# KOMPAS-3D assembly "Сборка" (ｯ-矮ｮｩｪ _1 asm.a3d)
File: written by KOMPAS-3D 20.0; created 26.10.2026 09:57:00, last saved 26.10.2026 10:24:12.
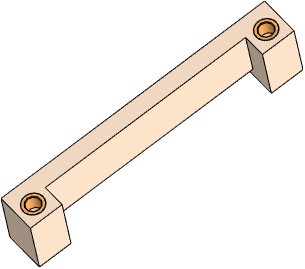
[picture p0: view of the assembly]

Document properties: Полное имя файла: D:\RicWork\Project-EPS32\box_compas\корпус\п-стойка_1 asm.a3d

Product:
- Part/product: Сборка
    Масса: 0.0139528
  - Component [detail]: Деталь  | Масса: 0.0133591; source file: п-стойка_1.m3d
  - Component [detail]: Деталь  | qty 4  | Масса: 0.000148431; source file: ..\прочее\Латунные рифленые гайки HUI JI.m3d

Referenced files in D:\RicWork\Project-EPS32\box_compas\корпус\: п-стойка_1.m3d
Referenced files in D:\RicWork\Project-EPS32\box_compas\прочее\: Латунные рифленые гайки HUI JI.m3d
